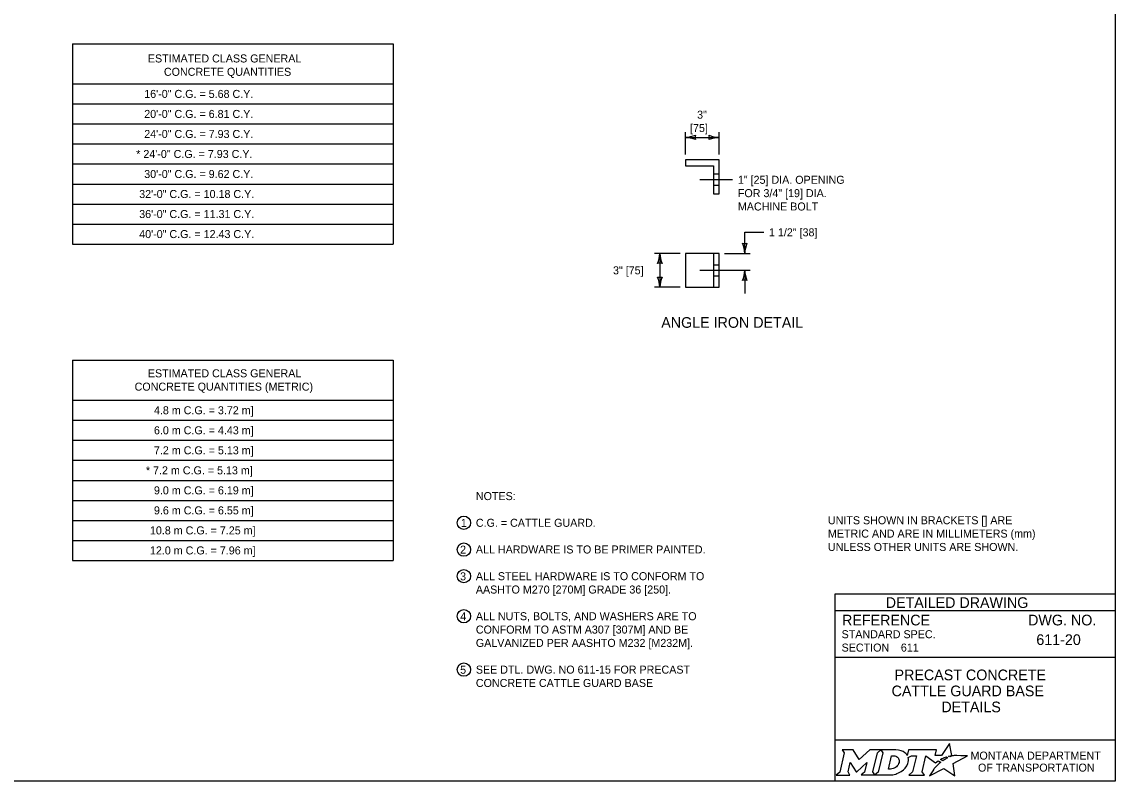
# Model space of a CAD drawing. Extents: x 49987.2 to 50044, y 49982.5 to 50011.4.
# Drawn here: x 50008.56 to 50016.75, y 49987.8 to 49993.49 of the extents above; entities that cross this region are included whole.
import ezdxf

# ---------------------------------------------------------------- set-up
doc = ezdxf.new("R2010")
doc.units = 0
for name, color, linetype in [('Default', 7, 'Continuous'), ('Level 1', 7, 'Continuous'), ('Level 2', 7, 'Continuous'), ('Level 3', 7, 'Continuous'), ('Level 4', 7, 'Continuous'), ('Level 5', 7, 'Continuous')]:
    doc.layers.add(name, color=color, linetype=linetype)

msp = doc.modelspace()

# ---------------------------------------------------------------- linework, layer by layer
at = {"layer": 'Default'}
for points in [[(50015.5126, 49987.9811), (50015.5023, 49987.9867), (50015.5139, 49987.9895), (50015.5255, 49987.9915), (50015.5081, 49988.0816), (50015.4486, 49987.9903), (50015.4013, 49987.9896), (50015.4116, 49988.0337), (50015.2024, 49988.0338), (50015.1923, 49987.9913), (50015.1865, 49987.9996)], [(50014.7056, 49988.0338), (50014.7197, 49988.0104), (50014.6862, 49987.8671), (50014.6605, 49987.8446), (50014.7621, 49987.8446), (50014.7486, 49987.8674), (50014.7648, 49987.9375), (50014.8085, 49987.8685), (50014.8138, 49987.8685), (50014.8889, 49987.938), (50014.8725, 49987.8669), (50014.8478, 49987.8449), (50014.9494, 49987.8449), (50014.9356, 49987.8682), (50014.9688, 49988.0106)], [(50014.9688, 49988.0106), (50014.9941, 49988.0338), (50014.9117, 49988.0338), (50014.8321, 49987.9608), (50014.7876, 49988.0335), (50014.7056, 49988.0338)], [(50015.1077, 49988.0338), (50014.9941, 49988.0338), (50015.0088, 49988.0109), (50014.9749, 49987.8671), (50014.9494, 49987.8449), (50015.06, 49987.8449)], [(50015.1317, 49987.9471), (50015.1305, 49987.939), (50015.1273, 49987.9297), (50015.1231, 49987.9215), (50015.1175, 49987.914), (50015.111, 49987.9071), (50015.1031, 49987.9008), (50015.0948, 49987.8961), (50015.0857, 49987.8922), (50015.0766, 49987.8899), (50015.0674, 49987.889), (50015.0515, 49987.889), (50015.0751, 49987.989), (50015.0911, 49987.989), (50015.0987, 49987.9884), (50015.1063, 49987.9865), (50015.1129, 49987.9835), (50015.119, 49987.9793), (50015.1238, 49987.9743), (50015.1275, 49987.9683), (50015.1302, 49987.9621), (50015.1318, 49987.9547), (50015.1318, 49987.9517), (50015.1317, 49987.9471)], [(50015.1991, 49987.9747), (50015.2237, 49987.9878), (50015.2606, 49987.9878), (50015.232, 49987.8673), (50015.2045, 49987.8446), (50015.3207, 49987.8446), (50015.3037, 49987.8675), (50015.3319, 49987.9877), (50015.4032, 49987.936), (50015.4243, 49987.9511), (50015.444, 49987.9402)], [(50015.3882, 49987.8843), (50015.3729, 49987.8599), (50015.3682, 49987.8524), (50015.3624, 49987.8438), (50015.3601, 49987.8395), (50015.4654, 49987.8926), (50015.5493, 49987.8375), (50015.5362, 49987.9302), (50015.6431, 49987.9886), (50015.5938, 49987.9894), (50015.5637, 49987.9898), (50015.5429, 49987.9901), (50015.5361, 49987.9886), (50015.5312, 49987.9874), (50015.5228, 49987.9851), (50015.5126, 49987.9811)], [(50015.4622, 49987.9535), (50015.4598, 49987.9518), (50015.4415, 49987.9614), (50015.4518, 49987.9671), (50015.4559, 49987.9693), (50015.4645, 49987.9733), (50015.4702, 49987.9759), (50015.4781, 49987.9789), (50015.4854, 49987.9816), (50015.4972, 49987.9742), (50015.4932, 49987.9721), (50015.4886, 49987.9696), (50015.4844, 49987.9674), (50015.4794, 49987.9645), (50015.4775, 49987.9634), (50015.4748, 49987.9618), (50015.4723, 49987.9604), (50015.47, 49987.9588), (50015.4674, 49987.957), (50015.4647, 49987.9552), (50015.4622, 49987.9535)], [(50015.4021, 49987.9004), (50015.4021, 49987.9004)], [(50015.1057, 49987.8522), (50015.1141, 49987.8548), (50015.1271, 49987.8602), (50015.1475, 49987.8712)]]:
    msp.add_lwpolyline(points, dxfattribs=at)
for centre in [(50011.8697, 49989.7343), (50011.8697, 49989.5332), (50011.8697, 49989.3343), (50011.8697, 49989.0344), (50011.8697, 49988.6342)]:
    msp.add_circle(centre, 0.05, dxfattribs=at)
for centre, radius, start, end in [((50015.1308, 49987.9554), 0.0709, 339.53292, 15.85821), ((50015.0868, 49987.9727), 0.1183, 300.91025, 339.13831)]:
    msp.add_arc(centre, radius, start, end, dxfattribs=at)
for centre, major_axis, ratio, start_param, end_param in [((50015.1056, 49987.9864), (0.0834, -0.0037), 0.568097, 0.61298, 1.570796), ((50015.1612, 49987.9937), (0.0361, -0.0295), 0.469099, 1.225588, 1.570796), ((50015.3952, 49987.8923), (-0.00694, -0.00806), 0.008222, 0, 3.137361), ((50015.4119, 49987.9106), (-0.0098, -0.0102), 0.016458, 3.141593, 6.279097), ((50015.4329, 49987.9305), (-0.0112, -0.0097), 0.021651, 3.157348, 6.283185), ((50015.0603, 49987.9932), (0, 0.1484), 0.987302, 3.139398, 3.456847)]:
    msp.add_ellipse(centre, major_axis=major_axis, ratio=ratio, start_param=start_param, end_param=end_param, dxfattribs=at)
at = {"layer": 'Level 1'}
for p, q in [((50013.7831, 49992.4524), (50013.53, 49992.4524)), ((50013.53, 49992.4524), (50013.53, 49992.4086)), ((50013.53, 49992.4086), (50013.7392, 49992.4086)), ((50013.7392, 49992.4086), (50013.7392, 49992.1993)), ((50013.7831, 49992.1993), (50013.7831, 49992.4524)), ((50013.7392, 49992.1993), (50013.7831, 49992.1993)), ((50013.7392, 49991.7523), (50013.7392, 49991.4992))]:
    msp.add_line(p, q, dxfattribs=at)
for points in [[(49999.3835, 49998.9992), (50016.7501, 49998.9992), (50016.7501, 49987.7988), (49999.3835, 49987.7988)], [(50013.53, 49991.4992), (50013.7831, 49991.4992), (50013.7831, 49991.7523), (50013.53, 49991.7523)]]:
    msp.add_lwpolyline(points, close=True, dxfattribs=at)
at = {"layer": 'Level 2'}
for p, q in [((50008.9378, 49993.3224), (50008.9378, 49991.8224)), ((50008.9378, 49993.3224), (50011.341, 49993.3224)), ((50011.341, 49993.3224), (50011.341, 49991.8224)), ((50008.9378, 49993.0224), (50011.341, 49993.0224)), ((50008.9378, 49992.8724), (50011.341, 49992.8724)), ((50008.9378, 49992.7224), (50011.341, 49992.7224)), ((50008.9378, 49992.5724), (50011.341, 49992.5724)), ((50008.9378, 49992.4224), (50011.341, 49992.4224)), ((50008.9378, 49992.2724), (50011.341, 49992.2724)), ((50008.9378, 49992.1224), (50011.341, 49992.1224)), ((50008.9378, 49991.9724), (50011.341, 49991.9724)), ((50008.9378, 49991.8224), (50011.341, 49991.8224)), ((50008.9378, 49990.9523), (50008.9378, 49989.4523)), ((50008.9378, 49990.9523), (50011.341, 49990.9523)), ((50011.341, 49990.9523), (50011.341, 49989.4523)), ((50008.9378, 49990.6523), (50011.341, 49990.6523)), ((50008.9378, 49990.5023), (50011.341, 49990.5023)), ((50008.9378, 49990.3523), (50011.341, 49990.3523)), ((50008.9378, 49990.2023), (50011.341, 49990.2023)), ((50008.9378, 49990.0523), (50011.341, 49990.0523)), ((50008.9378, 49989.9023), (50011.341, 49989.9023)), ((50008.9378, 49989.7523), (50011.341, 49989.7523)), ((50008.9378, 49989.6023), (50011.341, 49989.6023)), ((50008.9378, 49989.4523), (50011.341, 49989.4523))]:
    msp.add_line(p, q, dxfattribs=at)
at = {"layer": 'Level 3'}
for p, q in [((50013.53, 49992.4924), (50013.53, 49992.662)), ((50013.7831, 49992.4924), (50013.7831, 49992.662)), ((50013.53, 49992.622), (50013.7831, 49992.622)), ((50013.9746, 49991.7523), (50013.9746, 49991.9104)), ((50013.9746, 49991.9104), (50014.1164, 49991.9104)), ((50013.49, 49991.7523), (50013.2985, 49991.7523)), ((50013.3385, 49991.7523), (50013.3385, 49991.4992)), ((50013.8231, 49991.7523), (50014.0146, 49991.7523)), ((50013.9746, 49991.6257), (50013.9746, 49991.4523)), ((50013.49, 49991.4992), (50013.2985, 49991.4992))]:
    msp.add_line(p, q, dxfattribs=at)
for centre, radius, start, end in [((50013.5185, 49992.8547), 0.233, 272.82731, 292.07716), ((50013.6582, 49992.622), 0.0548, 162.13882, 197.86118), ((50013.7922, 49992.8441), 0.2223, 247.45601, 267.63952), ((50013.6549, 49992.622), 0.0548, 342.13882, 17.86118), ((50013.5208, 49992.3998), 0.2223, 67.45601, 87.63952), ((50013.7946, 49992.3893), 0.233, 92.82731, 112.07716), ((50013.9746, 49991.8805), 0.0548, 252.13882, 287.86118), ((50013.7418, 49991.7408), 0.233, 2.82731, 22.07716), ((50014.1967, 49991.7431), 0.2223, 157.45601, 177.63952), ((50013.1164, 49991.7615), 0.2223, 337.45601, 357.63952), ((50013.5712, 49991.7638), 0.233, 182.82731, 202.07716), ((50013.3385, 49991.6241), 0.0548, 72.13882, 107.86118), ((50013.3385, 49991.6274), 0.0548, 252.13882, 287.86118), ((50013.1058, 49991.4877), 0.233, 2.82731, 22.07716), ((50013.5606, 49991.49), 0.2223, 157.45601, 177.63952), ((50013.7418, 49991.6372), 0.233, 337.92284, 357.17269), ((50014.1967, 49991.6349), 0.2223, 182.36048, 202.54399), ((50013.9746, 49991.4975), 0.0548, 72.13882, 107.86118)]:
    msp.add_arc(centre, radius, start, end, dxfattribs=at)
at = {"layer": 'Level 4'}
for p, q in [((50013.7831, 49992.3462), (50013.7392, 49992.3462)), ((50013.7831, 49992.2617), (50013.7392, 49992.2617)), ((50013.7392, 49991.668), (50013.7831, 49991.668)), ((50013.7392, 49991.5835), (50013.7831, 49991.5835))]:
    msp.add_line(p, q, dxfattribs=at)
at = {"layer": 'Level 5'}
for p, q in [((50013.8831, 49992.3039), (50013.6392, 49992.3039)), ((50013.6392, 49991.6257), (50014.0146, 49991.6257)), ((50016.7501, 49989.1988), (50014.6501, 49989.1988)), ((50014.6501, 49989.1988), (50014.6501, 49987.7988)), ((50016.7501, 49989.0738), (50014.6501, 49989.0738)), ((50015.1444, 49988.7993), (50015.1444, 49988.7993)), ((50016.3862, 49988.8587), (50016.3862, 49988.8587)), ((50016.7501, 49988.7238), (50014.6501, 49988.7238)), ((50015.7001, 49988.4747), (50015.7001, 49988.4747)), ((50016.7501, 49988.1057), (50014.6501, 49988.1057))]:
    msp.add_line(p, q, dxfattribs=at)

# ---------------------------------------------------------------- texts
at = {"layer": 'Default'}
for s, p in [('1', (50011.8469, 49989.7032)), ('2', (50011.8415, 49989.5032)), ('3', (50011.8415, 49989.3032)), ('4', (50011.8427, 49989.0032)), ('5', (50011.8418, 49988.6032)), ('MONTANA DEPARTMENT', (50015.6663, 49987.96)), ('OF TRANSPORTATION', (50015.7225, 49987.87))]:
    msp.add_text(s, height=0.06, dxfattribs=at).set_placement(p)
at = {"layer": 'Level 2'}
for s, height, p in [('ESTIMATED CLASS GENERAL', 0.06, (50009.5016, 49993.1831)), ('CONCRETE QUANTITIES', 0.06, (50009.6221, 49993.0831)), ('16\'-0" C.G. = 5.68 C.Y.', 0.06, (50009.4746, 49992.9174)), ('20\'-0" C.G. = 6.81 C.Y.', 0.06, (50009.4746, 49992.7674)), ('3"', 0.06, (50013.6176, 49992.762)), ('[75]', 0.06, (50013.5647, 49992.662)), ('24\'-0" C.G. = 7.93 C.Y.', 0.06, (50009.4746, 49992.6174)), ('* 24\'-0" C.G. = 7.93 C.Y.', 0.06, (50009.4146, 49992.4674)), ('30\'-0" C.G. = 9.62 C.Y.', 0.06, (50009.4746, 49992.3174)), ('1" [25] DIA. OPENING', 0.06, (50013.9231, 49992.274)), ('FOR 3/4" [19] DIA.', 0.06, (50013.9231, 49992.174)), (' 32\'-0" C.G. = 10.18 C.Y.', 0.06, (50009.4146, 49992.1674)), (' 36\'-0" C.G. = 11.31 C.Y.', 0.06, (50009.4146, 49992.0174)), ('MACHINE BOLT', 0.06, (50013.9231, 49992.074)), (' 40\'-0" C.G. = 12.43 C.Y.', 0.06, (50009.4146, 49991.8674)), ('1 1/2" [38]', 0.06, (50014.1564, 49991.8804)), ('3" [75]', 0.06, (50012.9874, 49991.5957)), ('ANGLE IRON DETAIL', 0.08, (50013.3488, 49991.1951)), ('ESTIMATED CLASS GENERAL ', 0.06, (50009.5016, 49990.8243)), ('CONCRETE QUANTITIES (METRIC)', 0.06, (50009.4026, 49990.7243)), ('4.8 m C.G. = 3.72 m]', 0.06, (50009.5474, 49990.5473)), ('6.0 m C.G. = 4.43 m]', 0.06, (50009.5474, 49990.3973)), ('7.2 m C.G. = 5.13 m]', 0.06, (50009.5474, 49990.2473)), ('* 7.2 m C.G. = 5.13 m]', 0.06, (50009.4874, 49990.0973)), ('9.0 m C.G. = 6.19 m]', 0.06, (50009.5474, 49989.9473)), ('NOTES:', 0.06, (50011.9597, 49989.9043)), ('9.6 m C.G. = 6.55 m]', 0.06, (50009.5474, 49989.7973)), ('UNITS SHOWN IN BRACKETS [] ARE ', 0.06, (50014.5978, 49989.7233)), ('10.8 m C.G. = 7.25 m]', 0.06, (50009.5174, 49989.6473)), ('C.G. = CATTLE GUARD.', 0.06, (50011.9597, 49989.7043)), ('METRIC AND ARE IN MILLIMETERS (mm) ', 0.06, (50014.5978, 49989.6233)), ('12.0 m C.G. = 7.96 m]', 0.06, (50009.5174, 49989.4973)), ('ALL HARDWARE IS TO BE PRIMER PAINTED.', 0.06, (50011.9597, 49989.5043)), ('UNLESS OTHER UNITS ARE SHOWN.', 0.06, (50014.5978, 49989.5233)), ('ALL STEEL HARDWARE IS TO CONFORM TO', 0.06, (50011.9597, 49989.3043)), ('AASHTO M270 [270M] GRADE 36 [250].', 0.06, (50011.9597, 49989.2043)), ('ALL NUTS, BOLTS, AND WASHERS ARE TO', 0.06, (50011.9597, 49989.0043)), ('CONFORM TO ASTM A307 [307M] AND BE ', 0.06, (50011.9597, 49988.9043)), ('611-20', 0.08, (50016.1596, 49988.8187)), ('GALVANIZED PER AASHTO M232 [M232M].', 0.06, (50011.9597, 49988.8043)), ('611', 0.06, (50015.1444, 49988.7693)), ('SEE DTL. DWG. NO 611-15 FOR PRECAST', 0.06, (50011.9597, 49988.6043)), ('PRECAST CONCRETE', 0.08, (50015.097, 49988.5547)), ('CONCRETE CATTLE GUARD BASE', 0.06, (50011.9597, 49988.5043)), ('CATTLE GUARD BASE', 0.08, (50015.075, 49988.4347)), ('DETAILS', 0.08, (50015.4478, 49988.3147))]:
    msp.add_text(s, height=height, dxfattribs=at).set_placement(p)
at = {"layer": 'Level 5'}
for s, height, p in [('DETAILED DRAWING', 0.0799, (50015.0311, 49989.0963)), ('REFERENCE', 0.08, (50014.7037, 49988.9654)), ('DWG. NO.', 0.08, (50016.0979, 49988.9654)), ('STANDARD SPEC.', 0.06, (50014.7004, 49988.8694)), ('SECTION', 0.06, (50014.7004, 49988.7694))]:
    msp.add_text(s, height=height, dxfattribs=at).set_placement(p)

doc.saveas('drawing.dxf')
